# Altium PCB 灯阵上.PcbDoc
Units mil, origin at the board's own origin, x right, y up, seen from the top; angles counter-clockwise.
Board outline 2312.8 x 3212.02 mil, 2 copper layers (Top Layer, Bottom Layer); 34 components, 22 nets, 117 pads, 40 vias.
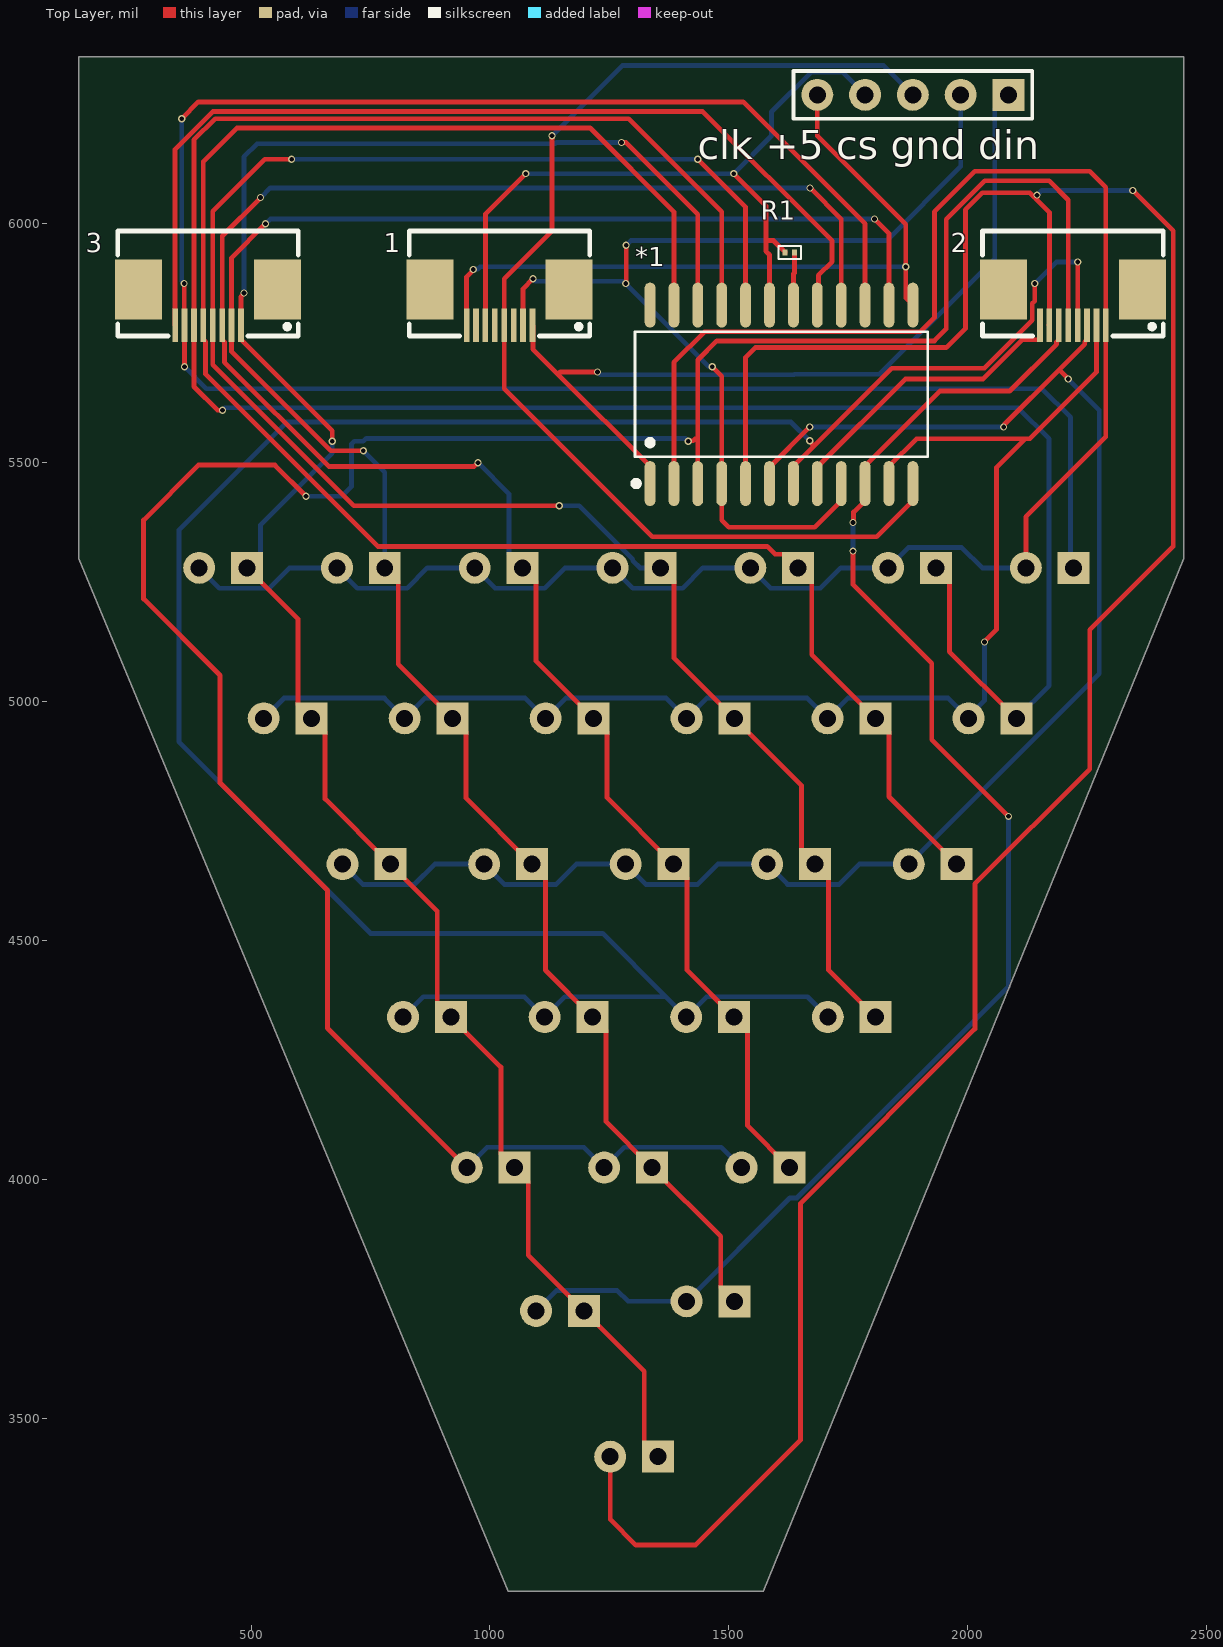
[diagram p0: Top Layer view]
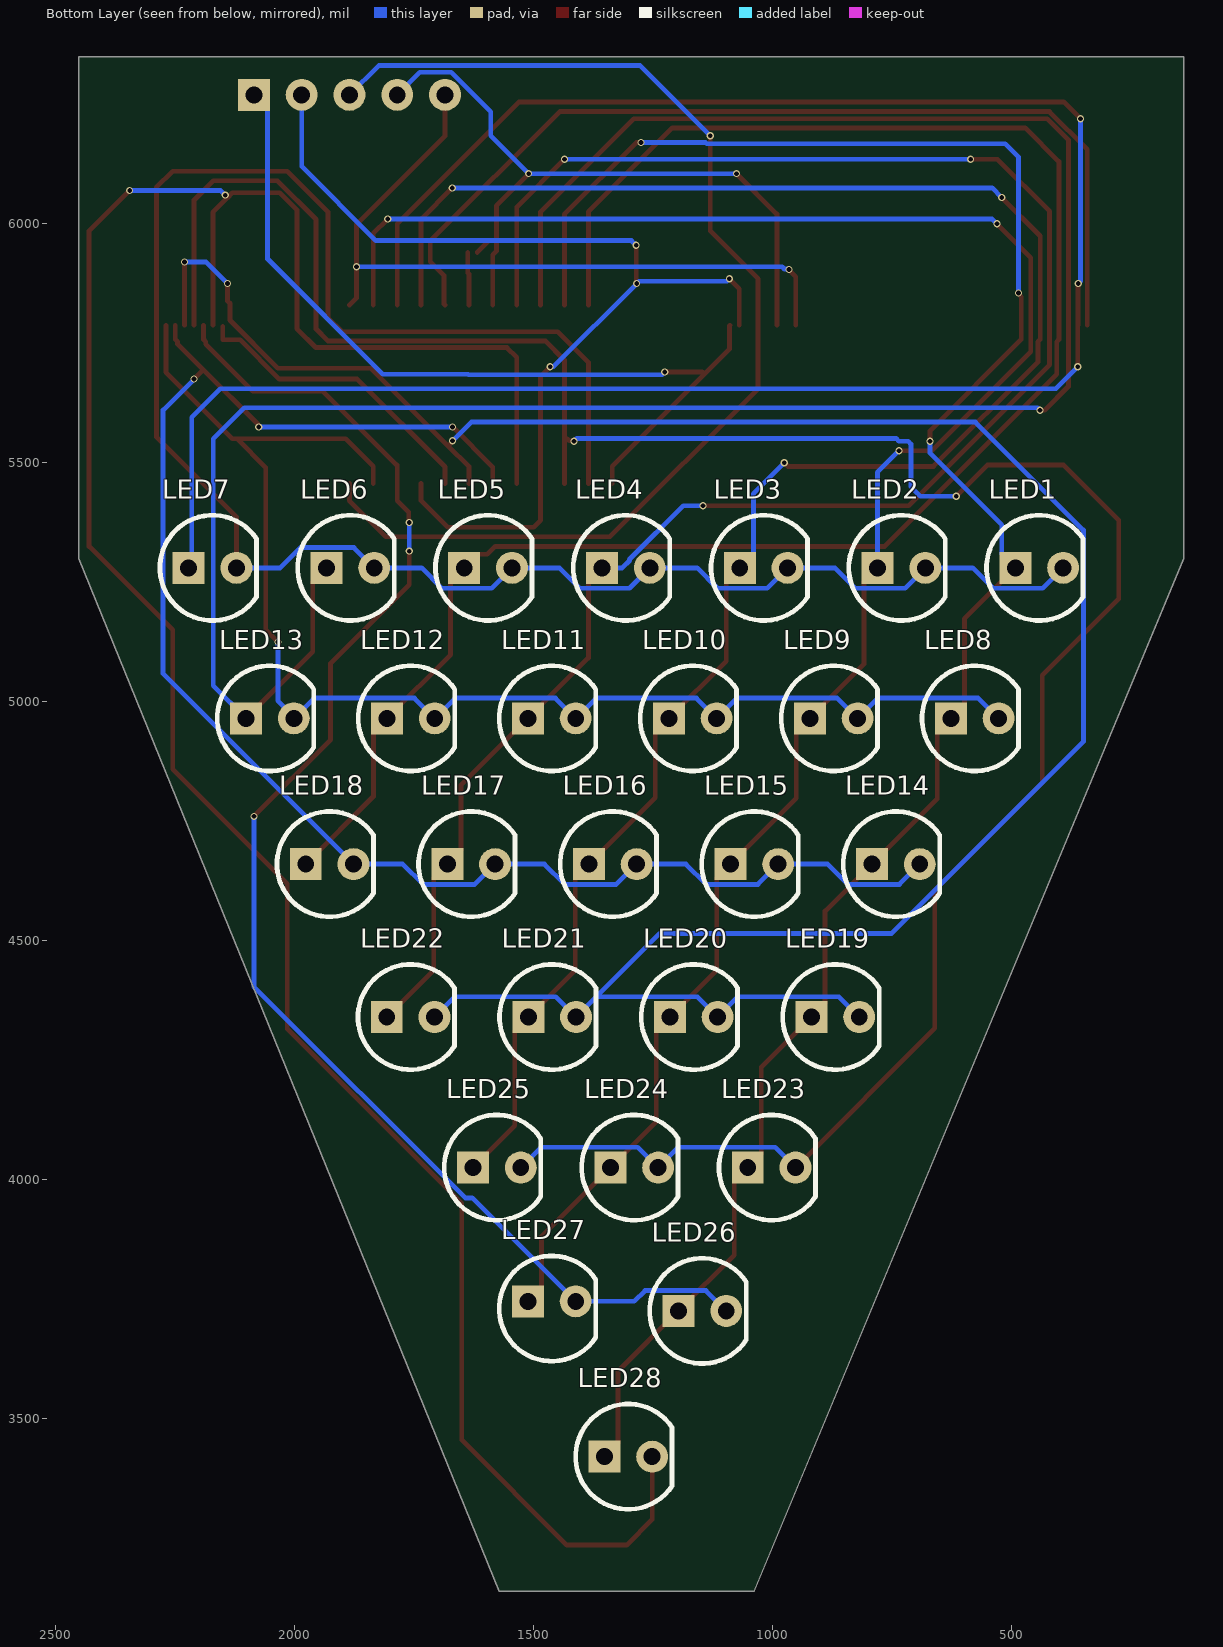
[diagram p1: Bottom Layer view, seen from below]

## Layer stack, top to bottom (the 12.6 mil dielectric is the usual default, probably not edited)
Top Solder: solder mask 0.4, Solder Resist, Dk 3.5
Top Layer: signal copper 1.4
Dielectric 1: dielectric 12.6, FR-4, Dk 4.8
Bottom Layer: signal copper 1.4
Bottom Solder: solder mask 0.4, Solder Resist, Dk 3.5

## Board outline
139.07,5299.31 139.07,6108.27 139.07,6100 cw(c134.06,6100) 139.07,6099.97 139.07,6100 139.07,6349.98 2451.87,6349.98 2451.87,5299.29 1571.63,3137.97 1038.35,3137.97

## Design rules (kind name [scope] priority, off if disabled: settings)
Clearance [All] p1: gap=4 ignorepadtopadclearanceinfootprint=TRUE
HoleToHoleClearance [All] p1: gap=4 allowstackedmicrovias=TRUE
MinimumSolderMaskSliver [All] p1: minsoldermaskwidth=0
PolygonConnect [All] p1: connectstyle=Relief reliefconductorwidth=10 reliefentries=4 polygonreliefangle="90 Angle" airgapwidth=10
RoutingVias [All] p1: holewidth=10 width=13 viastyle="Through Hole" minholewidth=8 minwidth=10 maxholewidth=10 maxwidth=15
SilkToSilkClearance [All] p1: silktosilkclearance=0
SilkToSolderMaskClearance [IsPad] p1: minsilkscreentomaskgap=0 clearancetoexposedcopper=TRUE
SolderMaskExpansion [All] p1: expansion=4
Width [All] p1: maxlimit=10 minlimit=10 preferedwidth=10
26 further rules are at their usual default settings.

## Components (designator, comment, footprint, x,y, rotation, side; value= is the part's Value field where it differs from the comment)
1 "ffc连接器" 排线座子 1040,5875 r0 top
2 "ffc连接器" 排线座子 2240,5875 r0 top
3 "ffc连接器" 排线座子 430,5875 r0 top
*1 "7219" 7219 -1452.39,5481.01 r0 top
"clk +5 cs gnd din" "Comment" HDR2.54-LI-5P 1885,6270 r180 top
LED1 "红色" "LED 5MM-B"#1 441.49,5280 r180 bottom
LED2 "红色" "LED 5MM-B"#1 729.82,5280 r180 bottom
LED3 "红色" "LED 5MM-B"#1 1018.15,5280 r180 bottom
LED4 "红色" "LED 5MM-B"#1 1306.49,5280 r180 bottom
LED5 "红色" "LED 5MM-B"#1 1594.82,5280 r180 bottom
LED6 "红色" "LED 5MM-B"#1 1883.15,5280 r180 bottom
LED7 "红色" "LED 5MM-B"#1 2171.49,5280 r180 bottom
LED8 "红色" "LED 5MM-B"#1 576.49,4965 r180 bottom
LED9 "红色" "LED 5MM-B"#1 871.49,4965 r180 bottom
LED10 "红色" "LED 5MM-B"#1 1166.49,4965 r180 bottom
LED11 "红色" "LED 5MM-B"#1 1461.49,4965 r180 bottom
LED12 "红色" "LED 5MM-B"#1 1756.49,4965 r180 bottom
LED13 "红色" "LED 5MM-B"#1 2051.49,4965 r180 bottom
LED14 "红色" "LED 5MM-B"#1 741.49,4660 r180 bottom
LED15 "红色" "LED 5MM-B"#1 1037.74,4660 r180 bottom
LED16 "红色" "LED 5MM-B"#1 1333.99,4660 r180 bottom
LED17 "红色" "LED 5MM-B"#1 1630.24,4660 r180 bottom
LED18 "红色" "LED 5MM-B"#1 1926.49,4660 r180 bottom
LED19 "红色" "LED 5MM-B"#1 868.21,4340 r180 bottom
LED20 "红色" "LED 5MM-B"#1 1164.46,4340 r180 bottom
LED21 "红色" "LED 5MM-B"#1 1460.71,4340 r180 bottom
LED22 "红色" "LED 5MM-B"#1 1756.96,4340 r180 bottom
LED23 "红色" "LED 5MM-B"#1 1001.49,4025 r180 bottom
LED24 "红色" "LED 5MM-B"#1 1288.99,4025 r180 bottom
LED25 "红色" "LED 5MM-B"#1 1576.49,4025 r180 bottom
LED26 "红色" "LED 5MM-B"#1 1146.49,3725 r180 bottom
LED27 "红色" "LED 5MM-B"#2 1461.49,3730 r180 bottom
LED28 "红色" "LED 5MM-B"#1 1301.49,3420 r180 bottom
R1 "10K" "R 0201_L" 1627.4,5940 r0 top

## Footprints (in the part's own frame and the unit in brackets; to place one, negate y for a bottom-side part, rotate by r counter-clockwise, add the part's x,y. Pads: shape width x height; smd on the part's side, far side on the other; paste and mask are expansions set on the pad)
7219 [mil]
  oval 22.6x94.02 smd: 1(2787.39,-24.55) 2(2837.39,-24.55) 3(2887.39,-24.55) 4(2937.39,-24.55) 5(2987.39,-24.55) 6(3037.39,-24.55) 7(3087.39,-24.55) 8(3137.39,-24.55) 9(3187.39,-24.55) 10(3237.39,-24.55) 11(3287.39,-24.55) 12(3337.39,-24.55) 13(3337.39,348.99) 14(3287.39,348.99) 15(3237.39,348.99) 16(3187.39,348.99) 17(3137.39,348.99) 18(3087.39,348.99) 19(3037.39,348.99) 20(2987.39,348.99) 21(2937.39,348.99) 22(2887.39,348.99) 23(2837.39,348.99) 24(2787.39,348.99)
  silkscreen extent 2752,-30 3369,293
HDR2.54-LI-5P [mm] "排针，5脚"
  rect 1.7x1.7 hole 0.9: 1(-5.08,0)
  round 1.7 hole 0.9: 2(-2.54,0) 3(0,0) 4(2.54,0) 5(5.08,0)
  silkscreen extent -6.35,-1.27 6.35,1.27, body extent -6.35,-1.27 6.35,1.27, height 8.5
"LED 5MM-B"#1 [mm] "蓝色5mm直插LED"
  rect 1.7x1.7 hole 0.9: 1(-1.27,0)
  round 1.7 hole 0.9: 2(1.27,0)
  silkscreen extent -2.8,-2.8 2.33,2.8, body extent -2.85,-2.85 2.45,2.85, height 8.75
"LED 5MM-B"#2 [mm] "蓝色5mm直插LED"
  rect 1.7x1.7 hole 0.9: 1(-1.27,0.381)
  round 1.7 hole 0.9: 2(1.27,0.381)
  silkscreen extent -2.8,-2.8 2.33,2.8, body extent -2.85,-2.85 2.45,2.85, height 8.75
"R 0201_L" [mm] "1/20W贴片电阻"
  rect 0.25x0.3 smd: 1(-0.25,0) 2(0.25,0)
  silkscreen extent -0.6,-0.35 0.6,0.35, body extent -0.3,-0.15 0.3,0.15, height 0.23
排线座子 [mm]
  rect 0.3x1.8 smd: 1(1.242,-2.22) 2(0.742,-2.22) 3(0.242,-2.22) 4(-0.258,-2.22) 5(-0.758,-2.22) 6(-1.258,-2.22) 7(-1.758,-2.22) 8(-2.258,-2.22)
  rect 2.5x3.2 smd: 9(-4.208,-0.32) 10(3.192,-0.32)
  silkscreen extent -5.31,-2.79 4.29,2.79

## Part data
1 2 3: library part 排线座子
LED1 LED2 LED3 LED4 LED5 LED6 LED7 LED8 LED9 LED10 LED11 LED12 LED13 LED14 LED15 LED16 LED17 LED18 LED19 LED20 LED21 LED22 LED23 LED24 LED25 LED26 LED27 LED28: library part LED-5MM, "5mm插件LED"
R1: library part R, "贴片电阻"

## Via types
v1: diameter 15, hole 10, Top Layer to Bottom Layer, 40 vias

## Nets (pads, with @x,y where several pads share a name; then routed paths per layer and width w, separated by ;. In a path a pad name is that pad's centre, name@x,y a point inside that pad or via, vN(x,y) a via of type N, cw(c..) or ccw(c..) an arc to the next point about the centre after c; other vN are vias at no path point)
0: 2.1 *1.2 LED1.2 LED2.2 LED3.2 LED4.2 LED5.2 LED6.2 LED7.2 | length 4273.4
  Top Layer w10: *1.2 1385,5710 1448.99,5773.99 1900.49,5773.99 1930,5803.5 1930,6025 2015,6110 2255,6110 2288.9,6076.1 2.1 2288.9,5553.9 2121.49,5386.49 LED7.2
  Bottom Layer w10: LED1.2 433.95,5237.54 538.12,5237.54 580.59,5280 LED2.2 722.28,5237.54 826.45,5237.54 868.92,5280 LED3.2 1010.62,5237.54 1114.79,5237.54 1157.25,5280 LED4.2 1298.95,5237.54 1403.12,5237.54 1445.59,5280 LED5.2 1587.28,5237.54 1691.45,5237.54 1733.92,5280 LED6.2 1875.62,5322.46 1987.54,5322.46 2030,5280 LED7.2
1: 2.2 *1.11 LED8.2 LED9.2 LED10.2 LED11.2 LED12.2 LED13.2 | length 2934.9
  Top Layer w10: *1.11 1835,5492.16 1892.84,5550 2120,5550 ; v1(2034.7,5125) 2060,5150.3 2060,5490 2120,5550 ; 2.2 2269.21,5689.21 2130,5550 2120,5550
  Bottom Layer w10: LED8.2 568.95,5007.46 779.02,5007.46 LED9.2 863.95,5007.46 1074.02,5007.46 LED10.2 1158.95,5007.46 1369.02,5007.46 LED11.2 1453.95,5007.46 1664.02,5007.46 LED12.2 1748.95,5007.46 1959.02,5007.46 LED13.2 2001.49,4969.02 2034.7,5002.24 v1(2034.7,5125)
2: 2.3 *1.6 LED14.2 LED15.2 LED16.2 LED17.2 LED18.2 | length 3399.1
  Top Layer w10: *1.6 1585,5490.86 v1(1669.14,5575) ; v1@2076.31,5580 2191.31,5695 ; v1(2210.16,5675) 2210.16,5676.15 2191.31,5695 ; 2.3 2249.53,5758.07 2244.75,5753.29 2244.75,5748.44 2191.31,5695
  Bottom Layer w10: LED14.2 733.95,4617.54 842.08,4617.54 884.54,4660 LED15.2 1030.2,4617.54 1138.33,4617.54 1180.79,4660 LED16.2 1326.45,4617.54 1434.58,4617.54 1477.04,4660 LED17.2 1622.7,4617.54 1730.83,4617.54 1773.29,4660 LED18.2 2275,5058.51 2275,5610.16 v1(2210.16,5675) ; v1(1669.14,5575) v1(2075,5575)
3: 2.4 *1.7 LED19.2 LED20.2 LED21.2 LED22.2 | length 5104.4
  Top Layer w10: *1.7 1635,5492.16 1677.84,5535 ; v1(1669.14,5545.86) 1669.14,5544.5 1677.84,5535.81 1677.84,5535 ; v1(2140,5875) 2140,5838.39 2135,5833.39 2135,5798.14 2034.7,5697.84 1840.68,5697.84 1677.84,5535 ; 2.4 2229.92,5787.68 2229.92,5919.92 v1(2230,5920)
  Bottom Layer w10: LED19.2 860.67,4382.46 1071.99,4382.46 LED20.2 1156.92,4382.46 1368.24,4382.46 ; v1(1669.14,5545.86) 1630,5585 575,5585 349.02,5359.02 349.02,4915.98 750,4515 1235.71,4515 1368.24,4382.46 ; LED22.2 1664.49,4382.46 1453.17,4382.46 LED21.2 1368.24,4382.46 ; v1(2140,5875) 2185,5920 v1(2230,5920)
4: 2.5 *1.3 LED23.2 LED24.2 LED25.2 | length 5224
  Top Layer w10: v1(615,5430) 550,5495 390,5495 275,5380 275,5215 435,5055 435,4830 660,4605 660,4316.49 LED23.2 ; v1(1415,5545) 1415.96,5545.96 1425.16,5545.96 1429.2,5550 1435,5550 ; *1.3 1435,5550 ; 2.5 2210.16,6049.84 2170,6090 2035.86,6090 1955,6009.14 1955,5780 1930,5755 1475,5755 1435,5715 1435,5550
  Bottom Layer w10: v1(615,5430) 690,5430 710,5450 710,5539.14 715.86,5545 735,5545 740.86,5550.86 1409.14,5550.86 v1(1415,5545) ; LED23.2 993.95,4067.46 1196.52,4067.46 LED24.2 1281.45,4067.46 1484.02,4067.46 LED25.2
5: 2.6 *1.10 LED26.2 LED27.2 | length 3071.2
  Top Layer w10: v1(1760,5315) 1760,5245 1924.52,5080.48 1924.52,4920.48 v1(2085,4760) ; v1(1760,5375) 1760.96,5375.96 1760.96,5396.7 1785,5420.75 *1.10 1785,5495 1786.35,5495 1941.35,5650 2087.26,5650 2185.69,5748.44 2185.69,5753.29 2190.47,5758.07 2.6
  Bottom Layer w10: LED26.2 1138.95,3767.46 1266.45,3767.46 1288.92,3745 LED27.2 1627.89,3961.4 1642.55,3961.4 2085,4403.86 v1(2085,4760) ; v1(1760,5315) v1(1760,5375)
6: 2.7 *1.5 LED28.2 | length 5264.5
  Top Layer w10: LED28.2 1251.49,3288.51 1305,3235 1430,3235 1650,3455 1650,3950 2015,4315 2015,4618.86 2255,4858.86 2255,5150 2430,5325 2430,5985 v1(2345,6070) ; *1.5 1535,5720.63 1555.37,5741 1955,5741 1994.9,5780.9 1994.9,6029.24 2030.66,6065 2130,6065 v1@2140,6055 ; 2142.5,6052.5 2170.79,6024.21 2170.79,5789.41 2169.88,5788.5 2.7 ; v1@2145,6055 v1(2145,6060)
  Bottom Layer w10: v1(2145,6060) 2155,6070 v1(2345,6070)
7: 2.8 *1.8 | length 637.9
  Top Layer w10: *1.8 1685,5491.08 1868.92,5675 2031.66,5675 2113.82,5757.16 2150.2,5757.16 2.8@2150.2,5785
+5: 1.6 "clk +5 cs gnd din.4" *1.19 R1.1 | length 1556.1
  Top Layer w10: 1.6 990.47,6020.47 v1(1075,6105) ; v1(1510,6105) 1577.5,6037.5 1577.5,5965 ; *1.19 1585,5935 1577.5,5942.5 1577.5,5965 ; R1.1 1617.56,5940.82 1593.38,5965 1577.5,5965
  Bottom Layer w10: v1(1075,6105) v1(1510,6105) 1589.18,6184.18 1589.18,6234.24 1672.04,6317.09 1737.91,6317.09 1785,6270
a: 3.2 *1.14 LED2.1 LED9.1 LED15.1 LED20.1 LED24.1 LED27.1 | length 4231.9
  Top Layer w10: v1(530,6000) 459.21,5929.21 3.2 459.21,5732.45 666.67,5525 v1(735,5525) ; LED2.1 808.28,5251.54 808.28,5078.2 LED9.1 949.95,4936.54 949.95,4797.79 LED15.1 1116.2,4631.54 1116.2,4438.26 LED20.1 1242.92,4311.54 1242.92,4121.06 LED24.1 1483.02,3880.96 1483.02,3773.46 LED27.1 ; v1(1805,6010) 1835,5980 *1.14
  Bottom Layer w10: v1(530,6000) 540,6010 v1(1805,6010) ; v1(735,5525) 780,5480 780,5280.18 LED2.1
b: 3.3 *1.16 LED3.1 LED10.1 LED16.1 LED21.1 LED25.1 | length 4179.1
  Top Layer w10: v1(520,6055) 439.53,5974.53 3.3 439.53,5758.07 444.31,5753.29 444.31,5710.69 662.84,5492.16 967.16,5492.16 v1(975,5500) ; LED3.1 1096.62,5251.54 1096.62,5084.87 LED10.1 1244.95,4936.54 1244.95,4799.04 LED16.1 1412.45,4631.54 1412.45,4438.26 LED21.1 1539.17,4311.54 1539.17,4112.31 LED25.1 ; v1(1670,6075) 1735,6010 *1.16
  Bottom Layer w10: v1(520,6055) 540,6075 v1(1670,6075) ; v1(975,5500) 1039.69,5435.31 1039.69,5308.46 LED3.1
c: 3.4 *1.20 LED4.1 LED11.1 LED17.1 LED22.1 | length 3968.4
  Top Layer w10: v1(585,6135) 528.9,6135 419.84,6025.94 3.4 419.84,5705.16 715,5410 v1(1145,5410) ; LED4.1 1384.95,5251.54 1384.95,5091.54 LED11.1 1651.77,4824.71 1651.77,4688.46 LED17.1 1708.7,4631.54 1708.7,4438.26 LED22.1 ; v1(1435,6135) 1535,6035 *1.20
  Bottom Layer w10: v1(585,6135) v1(1435,6135) ; v1(1145,5410) 1186.54,5410 1298.95,5297.59 1298.95,5295.04 1313.99,5280 LED4.1
clk: 1.8 "clk +5 cs gnd din.5" *1.13 | length 1552.7
  Top Layer w10: 1.8 951.1,5889.07 965,5902.97 v1(965,5904.32) ; 1685,6270 1685,6183.92 1870,5998.92 v1(1870,5910) 1870,5845 *1.13
  Bottom Layer w10: v1(965,5904.32) 965.96,5905.28 974.6,5905.28 979.32,5910 v1(1870,5910)
d: 3.5 *1.23 LED5.1 LED12.1 LED18.1 | length 3893.9
  Top Layer w10: *1.23 1385,6025 1209.32,6200.68 470.68,6200.68 400.16,6130.16 3.5 400.16,5758.07 404.94,5753.29 404.94,5685.06 765,5325 1580,5325 1596.54,5308.46 1616.35,5308.46 LED5.1 1673.28,5251.54 1673.28,5098.2 LED12.1 1834.95,4936.54 1834.95,4801.54 LED18.1
din: 1.1 "clk +5 cs gnd din.1" *1.1 | length 1807.5
  Top Layer w10: 1.1 1089.8,5786.69 1089.8,5737.36 1142.16,5685 ; v1(1225,5690) 1147.16,5690 1142.16,5685 ; *1.1 1335,5492.16 1142.16,5685
  Bottom Layer w10: v1(1225,5690) 1230.71,5684.29 1636.23,5684.29 1636.94,5685 1815,5685 2056.54,5926.54 2056.54,6241.54 2085,6270
e: 3.6 *1.21 LED6.1 LED13.1 | length 4751.8
  Top Layer w10: v1(440,5610) 430,5610 380.47,5659.53 3.6 380.47,6175.47 425,6220 1290,6220 1485,6025 *1.21 ; LED6.1 1961.62,5251.54 1961.62,5104.87 LED13.1
  Bottom Layer w10: v1(440,5610) 445,5615 2105,5615 2170,5550 2170,5033.51 LED13.1
f: 3.7 *1.15 LED7.1 | length 4457.4
  Top Layer w10: v1(355,6220) 390,6255 1530,6255 1785,6000 *1.15 ; v1(360,5875) 360.39,5874.61 360.39,5787.99 3.7 v1(360.79,5700.79)
  Bottom Layer w10: v1(355,6220) 355,5880 v1(360,5875) ; v1(360.79,5700.79) 406.57,5655 2155,5655 2215,5595 2215,5286.49 LED7.1
g: 3.8 *1.17 | length 2034.9
  Top Layer w10: 3.8 341.1,6155.9 420.2,6235 1445,6235 1715.86,5964.14 1715.86,5920.42 1687.41,5891.97 1687.41,5832.41 *1.17
gnd: 1.2 "clk +5 cs gnd din.2" *1.4 *1.9 | length 2200.4
  Top Layer w10: 1.2 1069.21,5864.21 v1(1090,5885) ; v1(1283.99,5875) 1285,5876.01 v1(1285,5955) ; v1(1465,5700.79) 1485,5680.79 *1.4 1485,5379.55 1499.55,5365 1679.25,5365 1735,5420.75 *1.9
  Bottom Layer w10: v1(1090,5885) 1095,5880 1278.99,5880 v1(1283.99,5875) 1458.2,5700.79 v1(1465,5700.79) ; v1(1285,5955) 1295,5965 1830,5965 1985,6120 1985,6270
load: 1.4 "clk +5 cs gnd din.3" *1.12 | length 2462.4
  Top Layer w10: v1(1130,6184.18) 1130,5985 1029.84,5884.84 1.4 1029.84,5655.16 1340,5345 1809.25,5345 1885,5420.75 *1.12
  Bottom Layer w10: v1(1130,6184.18) 1276.91,6331.09 1823.91,6331.09 1885,6270
Net*1_18: *1.18 R1.2 | length 110.9
  Top Layer w10: *1.18 1635,5895 1637.24,5897.24 R1.2
p: 3.1 *1.22 LED1.1 LED8.1 LED14.1 LED19.1 LED23.1 LED26.1 LED28.1 | length 4446.4
  Top Layer w10: v1(485,5855) 485,5853.65 478.9,5847.54 3.1 478.9,5758.07 670,5566.97 v1(670,5545) ; LED1.1 598.02,5173.46 598.02,4993.46 LED8.1 654.95,4936.54 654.95,4796.54 LED14.1 889.74,4561.74 889.74,4368.46 LED19.1 1023.02,4235.19 1023.02,4053.46 LED23.1 1079.95,3996.54 1079.95,3841.54 LED26.1 1323.02,3598.46 1323.02,3448.46 LED28.1 ; v1(1275,6170) 1285,6170 1435,6020 *1.22
  Bottom Layer w10: v1(485,5855) 485,6140 512.68,6167.68 1136.83,6167.68 1139.15,6170 v1(1275,6170) ; LED1.1 519.95,5308.46 519.95,5369.95 670,5520 v1(670,5545)
pads on no net: 1.3 1.5 1.7 1.9 1.10 2.9 2.10 3.9 3.10 *1.24

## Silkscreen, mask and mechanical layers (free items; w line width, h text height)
Mechanical 1:
  lines w10: 134.06,6100 134.06,6360 2456.89,6360 2456.89,6109.29 2456.89,5298.31 1575,3132.95 1035,3132.95 134.06,5298.31 134.06,6108.27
